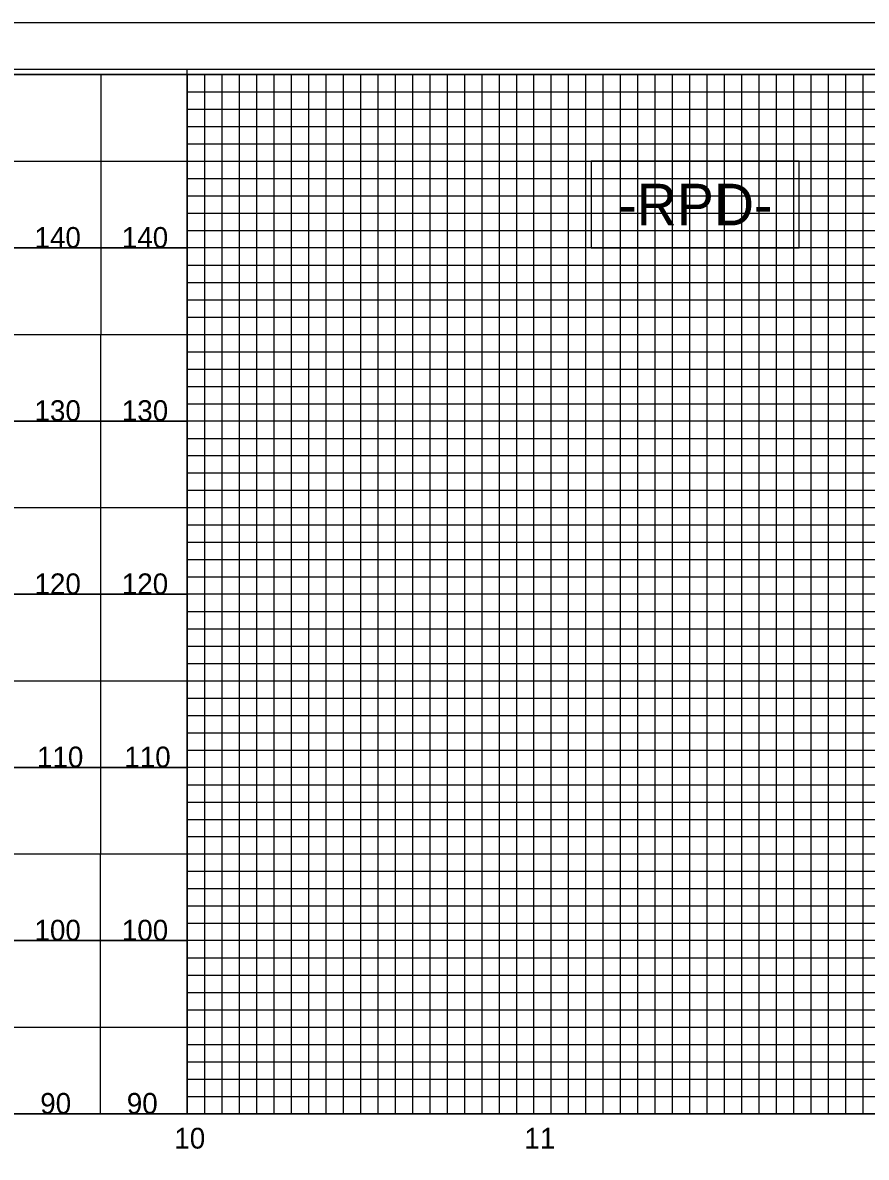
# Model space of a CAD drawing. Extents: x -130 to 890, y -29895 to -29235.
# Drawn here: x 402.5 to 646, y -29562.3 to -29234.8 of the extents above; entities that cross this region are included whole.
import ezdxf

# ---------------------------------------------------------------- set-up
doc = ezdxf.new("R2010")
doc.units = 0
for name, color, linetype in [('Exist Vertical Profile Horizontal Axis Label Major', 7, 'Continuous'), ('Exist Vertical Profile Vertical Axis Label', 7, 'Continuous'), ('Prop Grid Mask', 7, 'Continuous'), ('Prop PFL Text', 7, 'Continuous'), ('Scratch_Level_0', 7, 'Continuous'), ('Sheet Cutting Line CELL', 7, 'Continuous'), ('Sheet Layout Profile Border Port 1', 7, 'Continuous'), ('Sheet Plot Border Inside CELL', 7, 'Continuous'), ('Sheet Plot Border Outside CELL', 7, 'Continuous'), ('Sheet Profile CELL', 7, 'Continuous'), ('Sheet Profile Grid Major CELL', 7, 'Continuous'), ('Sheet Profile Grid Middle CELL', 7, 'Continuous'), ('Sheet Profile Grid Minor CELL', 7, 'Continuous')]:
    doc.layers.add(name, color=color, linetype=linetype)

msp = doc.modelspace()

# ---------------------------------------------------------------- linework, layer by layer
at = {"layer": 'Prop Grid Mask'}
msp.add_lwpolyline([(566.64, -29299.75), (626.64, -29299.75), (626.64, -29274.75), (566.64, -29274.75)], close=True, dxfattribs=at)
at = {"layer": 'Prop PFL Text'}
msp.add_lwpolyline([(566.64, -29299.75), (626.64, -29299.75), (626.64, -29274.75), (566.64, -29274.75)], close=True, dxfattribs=at)
at = {"layer": 'Scratch_Level_0'}
msp.add_line((450, -29549.75), (450, -29248.22), dxfattribs=at)
msp.add_lwpolyline([(450, -29249.75), (750, -29249.75), (749.97, -29346.38), (840, -29346.38), (840, -29549.75), (450, -29549.75)], close=True, dxfattribs=at)
at = {"layer": 'Sheet Cutting Line CELL'}
msp.add_line((889.8, -29234.75), (-130.2, -29234.75), dxfattribs=at)
at = {"layer": 'Sheet Layout Profile Border Port 1'}
msp.add_lwpolyline([(0, -29249.75), (749.97, -29249.75), (749.97, -29369.63), (840, -29369.75), (840, -29549.75), (0, -29549.75)], close=True, dxfattribs=at)
at = {"layer": 'Sheet Plot Border Inside CELL'}
msp.add_lwpolyline([(-122.4, -29881.28), (877.5, -29881.28), (877.5, -29248.22), (-122.4, -29248.22)], close=True, dxfattribs=at)
at = {"layer": 'Sheet Plot Border Outside CELL'}
msp.add_lwpolyline([(-130.2, -29894.75), (889.8, -29894.75), (889.8, -29234.75), (-130.2, -29234.75)], close=True, dxfattribs=at)
at = {"layer": 'Sheet Profile CELL'}
msp.add_line((-30, -29549.75), (870, -29549.75), dxfattribs=at)
msp.add_lwpolyline([(870, -29249.75), (-30, -29249.75), (-30, -29879.75), (870, -29879.75)], close=True, dxfattribs=at)
at = {"layer": 'Sheet Profile Grid Major CELL'}
for p, q in [((424.93, -29549.75), (425.2, -29249.75)), ((450, -29249.75), (450, -29549.75)), ((475, -29249.75), (475, -29549.75)), ((500, -29249.75), (500, -29549.75)), ((525, -29249.75), (525, -29549.75)), ((550, -29249.75), (550, -29549.75)), ((575, -29249.75), (575, -29549.75)), ((600, -29249.75), (600, -29549.75)), ((625, -29249.75), (625, -29549.75)), ((-30, -29274.75), (750, -29274.75)), ((400, -29274.75), (450, -29274.75)), ((750, -29299.75), (-30, -29299.75)), ((400, -29299.75), (450, -29299.75)), ((-30, -29324.75), (750, -29324.75)), ((400, -29324.75), (450, -29324.75)), ((750, -29349.75), (-30, -29349.75)), ((400, -29349.75), (450, -29349.75)), ((-30, -29374.75), (870, -29374.75)), ((400, -29374.75), (450, -29374.75)), ((870, -29399.75), (-30, -29399.75)), ((400, -29399.75), (450, -29399.75)), ((-30, -29424.75), (870, -29424.75)), ((400, -29424.75), (450, -29424.75)), ((870, -29449.75), (-30, -29449.75)), ((400, -29449.75), (450, -29449.75)), ((-30, -29474.75), (870, -29474.75)), ((400, -29474.75), (450, -29474.75)), ((870, -29499.75), (-30, -29499.75)), ((400, -29499.75), (450, -29499.75)), ((-30, -29524.75), (870, -29524.75)), ((400, -29524.75), (449.91, -29524.75))]:
    msp.add_line(p, q, dxfattribs=at)
at = {"layer": 'Sheet Profile Grid Middle CELL'}
for p, q in [((450, -29254.75), (750, -29254.75)), ((450, -29259.75), (750, -29259.75)), ((450, -29264.75), (750, -29264.75)), ((450, -29269.75), (750, -29269.75)), ((450, -29279.75), (750, -29279.75)), ((450, -29284.75), (750, -29284.75)), ((450, -29289.75), (750, -29289.75)), ((450, -29294.75), (750, -29294.75)), ((450, -29304.75), (750, -29304.75)), ((450, -29309.75), (750, -29309.75)), ((450, -29314.75), (750, -29314.75)), ((450, -29319.75), (750, -29319.75)), ((450, -29329.75), (750, -29329.75)), ((450, -29334.75), (750, -29334.75)), ((450, -29339.75), (750, -29339.75)), ((450, -29344.75), (750, -29344.75)), ((450, -29354.75), (750, -29354.75)), ((450, -29359.75), (750, -29359.75)), ((450, -29364.75), (750, -29364.75)), ((450, -29369.75), (840, -29369.75)), ((450, -29379.75), (840, -29379.75)), ((450, -29384.75), (840, -29384.75)), ((450, -29389.75), (840, -29389.75)), ((450, -29394.75), (840, -29394.75)), ((450, -29404.75), (840, -29404.75)), ((450, -29409.75), (840, -29409.75)), ((450, -29414.75), (840, -29414.75)), ((450, -29419.75), (840, -29419.75)), ((450, -29429.75), (840, -29429.75)), ((450, -29434.75), (840, -29434.75)), ((450, -29439.75), (840, -29439.75)), ((450, -29444.75), (840, -29444.75)), ((450, -29454.75), (840, -29454.75)), ((450, -29459.75), (840, -29459.75)), ((450, -29464.75), (840, -29464.75)), ((450, -29469.75), (840, -29469.75)), ((450, -29479.75), (840, -29479.75)), ((450, -29484.75), (840, -29484.75)), ((450, -29489.75), (840, -29489.75)), ((450, -29494.75), (840, -29494.75)), ((450, -29504.75), (840, -29504.75)), ((450, -29509.75), (840, -29509.75)), ((450, -29514.75), (840, -29514.75)), ((450, -29519.75), (840, -29519.75)), ((450, -29529.75), (840, -29529.75)), ((450, -29534.75), (840, -29534.75)), ((450, -29539.75), (840, -29539.75)), ((450, -29544.75), (840, -29544.75))]:
    msp.add_line(p, q, dxfattribs=at)
at = {"layer": 'Sheet Profile Grid Minor CELL'}
for p, q in [((455, -29249.75), (455, -29549.75)), ((460, -29249.75), (460, -29549.75)), ((465, -29249.75), (465, -29549.75)), ((470, -29249.75), (470, -29549.75)), ((480, -29249.75), (480, -29549.75)), ((485, -29249.75), (485, -29549.75)), ((490, -29249.75), (490, -29549.75)), ((495, -29249.75), (495, -29549.75)), ((505, -29249.75), (505, -29549.75)), ((510, -29249.75), (510, -29549.75)), ((515, -29249.75), (515, -29549.75)), ((520, -29249.75), (520, -29549.75)), ((530, -29249.75), (530, -29549.75)), ((535, -29249.75), (535, -29549.75)), ((540, -29249.75), (540, -29549.75)), ((545, -29249.75), (545, -29549.75)), ((555, -29249.75), (555, -29549.75)), ((560, -29249.75), (560, -29549.75)), ((565, -29249.75), (565, -29549.75)), ((570, -29249.75), (570, -29549.75)), ((580, -29249.75), (580, -29549.75)), ((585, -29249.75), (585, -29549.75)), ((590, -29249.75), (590, -29549.75)), ((595, -29249.75), (595, -29549.75)), ((605, -29249.75), (605, -29549.75)), ((610, -29249.75), (610, -29549.75)), ((615, -29249.75), (615, -29549.75)), ((620, -29249.75), (620, -29549.75)), ((630, -29249.75), (630, -29549.75)), ((635, -29249.75), (635, -29549.75)), ((640, -29249.75), (640, -29549.75)), ((645, -29249.75), (645, -29549.75))]:
    msp.add_line(p, q, dxfattribs=at)

# ---------------------------------------------------------------- texts
at = {"layer": 'Exist Vertical Profile Horizontal Axis Label Major'}
for s, p in [('10', (446.27, -29559.81)), ('11', (547.32, -29559.81))]:
    msp.add_text(s, height=6, dxfattribs=at).set_placement(p)
at = {"layer": 'Exist Vertical Profile Vertical Axis Label'}
for s, p in [('140', (405.9, -29299.75)), ('140', (431.11, -29299.75)), ('130', (405.9, -29349.75)), ('130', (431.11, -29349.75)), ('120', (405.9, -29399.75)), ('120', (431.11, -29399.75)), ('110', (406.62, -29449.75)), ('110', (431.83, -29449.75)), ('100', (405.9, -29499.75)), ('100', (431.11, -29499.75)), ('90', (407.56, -29549.75)), ('90', (432.55, -29549.75))]:
    msp.add_text(s, height=6, dxfattribs=at).set_placement(p)
at = {"layer": 'Prop PFL Text'}
msp.add_text('-RPD-', height=12, dxfattribs=at).set_placement((574.39, -29293.25))

doc.saveas('drawing.dxf')
